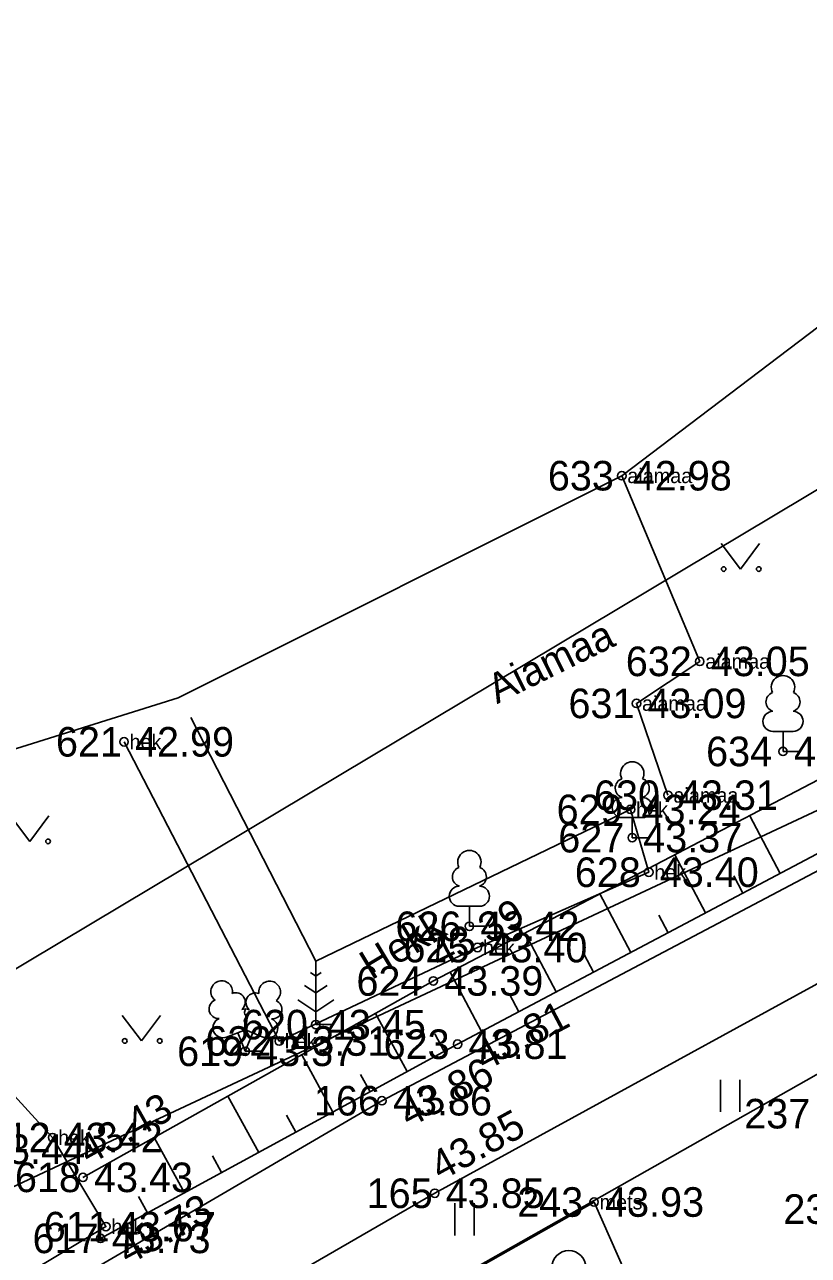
# Model space of a CAD drawing. Extents: x 505800 to 507326, y 6540058 to 6542128.
# Drawn here: x 506386.44 to 506404.99, y 6540355.67 to 6540384.81 of the extents above; entities that cross this region are included whole.
import ezdxf

# ---------------------------------------------------------------- set-up
doc = ezdxf.new("R2010")
doc.units = 0
for name, color, linetype in [('HALJASTUS', 7, 'Continuous'), ('KORGUS-EH2000', 7, 'Continuous'), ('MAAMUDEL', 7, 'Continuous'), ('MOOTKORG-EH2000', 7, 'Continuous'), ('MOOTMPUNKT', 7, 'Continuous'), ('MOOTNR', 7, 'Continuous'), ('MOOTPIIR', 7, 'Continuous'), ('MPOHULIIN', 7, 'Continuous'), ('PIIR', 7, 'Continuous'), ('PUU', 7, 'Continuous'), ('RELJEEF', 7, 'Continuous'), ('TEE', 7, 'Continuous')]:
    doc.layers.add(name, color=color, linetype=linetype)

msp = doc.modelspace()

# ---------------------------------------------------------------- linework, layer by layer
at = {"layer": 'HALJASTUS'}
for p, q in [((506402.92, 6540372.527), (506403.383, 6540371.92)), ((506403.383, 6540371.92), (506403.829, 6540372.527)), ((506386.104, 6540366.077), (506386.568, 6540365.471)), ((506386.568, 6540365.471), (506387.013, 6540366.077)), ((506388.747, 6540361.35), (506389.21, 6540360.744)), ((506389.21, 6540360.744), (506389.656, 6540361.35)), ((506402.906, 6540359.823), (506402.906, 6540359.062)), ((506403.361, 6540359.823), (506403.361, 6540359.062)), ((506396.621, 6540356.899), (506396.621, 6540356.137)), ((506397.076, 6540356.899), (506397.076, 6540356.137))]:
    msp.add_line(p, q, dxfattribs=at)
for points in [[(506400.572, 6540374.13), (506402.416, 6540369.732), (506400.919, 6540368.738), (506401.664, 6540366.563)], [(506390.376, 6540368.401), (506393.333, 6540362.631), (506400.779, 6540366.227), (506401.21, 6540364.74), (506397.155, 6540362.956), (506392.467, 6540360.742), (506388.793, 6540367.828)], [(506383.074, 6540362.871), (506387.104, 6540358.456), (506388.363, 6540356.347), (506379.473, 6540351.019), (506371.247, 6540346.037), (506370.193, 6540346.236), (506368.863, 6540348.749), (506383.542, 6540357.221), (506381.795, 6540361.969), (506383.074, 6540362.871)], [(506391.999, 6540341.498), (506392.008, 6540346.055), (506393.81, 6540353.469), (506399.916, 6540356.93), (506402.307, 6540351.523), (506409.831, 6540355.263), (506411.426, 6540354.112)]]:
    msp.add_lwpolyline(points, dxfattribs=at)
for centre, radius in [((506402.982, 6540371.92), 0.055), ((506403.811, 6540371.92), 0.055), ((506386.995, 6540365.471), 0.055), ((506388.809, 6540360.744), 0.055), ((506389.638, 6540360.744), 0.055), ((506399.317, 6540355.381), 0.4)]:
    msp.add_circle(centre, radius, dxfattribs=at)
at = {"layer": 'KORGUS-EH2000'}
for centre in [(506400.572, 6540374.13), (506402.416, 6540369.732), (506400.919, 6540368.738), (506388.793, 6540367.828), (506404.386, 6540367.6), (506401.664, 6540366.563), (506400.779, 6540366.227), (506400.819, 6540365.558), (506401.21, 6540364.74), (506396.965, 6540363.459), (506397.155, 6540362.956), (506396.112, 6540362.165), (506393.333, 6540361.131), (506392.467, 6540360.742), (506396.686, 6540360.667), (506391.66, 6540360.499), (506394.897, 6540359.329), (506387.104, 6540358.456), (506387.822, 6540357.514), (506396.144, 6540357.137), (506399.916, 6540356.93), (506388.363, 6540356.347), (506388.239, 6540356.069)]:
    msp.add_circle(centre, 0.1, dxfattribs=at)
at = {"layer": 'MOOTMPUNKT'}
for centre in [(506400.572, 6540374.13), (506402.416, 6540369.732), (506400.919, 6540368.738), (506388.793, 6540367.828), (506404.386, 6540367.6), (506401.664, 6540366.563), (506400.779, 6540366.227), (506400.819, 6540365.558), (506401.21, 6540364.74), (506396.965, 6540363.459), (506397.155, 6540362.956), (506396.112, 6540362.165), (506393.333, 6540361.131), (506392.467, 6540360.742), (506396.686, 6540360.667), (506391.66, 6540360.499), (506394.897, 6540359.329), (506387.104, 6540358.456), (506387.822, 6540357.514), (506396.144, 6540357.137), (506399.916, 6540356.93), (506388.363, 6540356.347), (506388.239, 6540356.069)]:
    msp.add_circle(centre, 0.1, dxfattribs=at)
at = {"layer": 'MOOTPIIR'}
msp.add_lwpolyline([(506240.253, 6540270.959), (506245.955, 6540263.864), (506266.133, 6540270.794), (506275.983, 6540276.683), (506285.511, 6540285.657), (506298.843, 6540299.878), (506301.086, 6540304.525), (506297.722, 6540312.738), (506305.023, 6540318.445), (506309.38, 6540311.746), (506312.325, 6540315.185), (506338.029, 6540330.648), (506336.908, 6540340.183), (506347.357, 6540347.554), (506370.89, 6540361.705), (506382.389, 6540366.462), (506390.076, 6540368.866), (506400.572, 6540374.13), (506410.565, 6540381.71), (506441.143, 6540393.151), (506453.59, 6540403.335), (506461.402, 6540393.473), (506495.448, 6540402.285)], dxfattribs=at)
at = {"layer": 'MPOHULIIN'}
msp.add_line((506372.493, 6540354.233), (506416.453, 6540380.536), dxfattribs=at)
at = {"layer": 'PIIR'}
msp.add_lwpolyline([(506326.14, 6540370.11), (506324.04, 6540375.18), (506354.05, 6540393.57), (506395.54, 6540418.74), (506427.6, 6540438.79), (506429.21, 6540436.36), (506458.7, 6540391.28), (506340.34, 6540335.82)], close=True, dxfattribs=at)
for points in [[(506215.95, 6540254.34), (506268.55, 6540273.9), (506274.54, 6540277.85), (506304.35, 6540308.95), (506340.34, 6540335.82), (506458.7, 6540391.28), (506563.96, 6540420.02)], [(506497.85, 6540391.32), (506462.8, 6540384.69), (506453.27, 6540382.76), (506413.82, 6540364.84), (506374.55, 6540342.6), (506353.59, 6540332.53), (506318.07, 6540309.28), (506308, 6540301.95), (506281.65, 6540275.05), (506272.39, 6540267.75), (506224.13, 6540249.92)], [(506224.13, 6540249.92), (506272.39, 6540267.75), (506281.65, 6540275.05), (506308, 6540301.95), (506318.07, 6540309.28), (506353.59, 6540332.53), (506374.55, 6540342.6), (506413.82, 6540364.84), (506453.27, 6540382.76), (506462.8, 6540384.69), (506495.14, 6540337.45), (506342.85, 6540237.27), (506260.72, 6540195.9), (506215.68, 6540179.69)]]:
    msp.add_lwpolyline(points, dxfattribs=at)
at = {"layer": 'PUU'}
for p, q in [((506404.626, 6540368.075), (506404.146, 6540368.075)), ((506404.386, 6540367.6), (506404.386, 6540368.075)), ((506404.766, 6540367.6), (506404.386, 6540367.6)), ((506401.059, 6540366.033), (506400.579, 6540366.033)), ((506400.819, 6540365.558), (506400.819, 6540366.033)), ((506401.199, 6540365.558), (506400.819, 6540365.558)), ((506397.205, 6540363.934), (506396.725, 6540363.934)), ((506396.965, 6540363.459), (506396.965, 6540363.934)), ((506397.345, 6540363.459), (506396.965, 6540363.459)), ((506393.333, 6540362.281), (506393.208, 6540362.364)), ((506393.333, 6540362.631), (506393.333, 6540361.131)), ((506393.457, 6540362.364), (506393.333, 6540362.281)), ((506393.333, 6540361.881), (506393.066, 6540362.059)), ((506393.599, 6540362.059), (506393.333, 6540361.881)), ((506392.909, 6540361.72), (506393.333, 6540361.437)), ((506393.333, 6540361.437), (506393.757, 6540361.72)), ((506391.22, 6540360.834), (506391.665, 6540361.009)), ((506391.66, 6540360.499), (506391.485, 6540360.939)), ((506391.66, 6540360.499), (506391.84, 6540360.939)), ((506391.665, 6540361.009), (506392.105, 6540360.829)), ((506393.693, 6540361.131), (506393.333, 6540361.131)), ((506392.04, 6540360.499), (506391.66, 6540360.499))]:
    msp.add_line(p, q, dxfattribs=at)
msp.add_lwpolyline([(506391.665, 6540361.504), (506391.645, 6540361.429), (506391.645, 6540361.409), (506391.655, 6540361.379), (506391.675, 6540361.344), (506391.68, 6540361.324), (506391.665, 6540361.289), (506391.64, 6540361.239), (506391.635, 6540361.214), (506391.64, 6540361.199), (506391.65, 6540361.169), (506391.685, 6540361.109), (506391.69, 6540361.089), (506391.685, 6540361.069), (506391.67, 6540361.034), (506391.665, 6540361.009)], dxfattribs=at)
for centre, radius, start, end in [((506404.386, 6540369.12), 0.277, 332.5799, 207.4201), ((506404.216, 6540368.773), 0.233, 109.0217, 253.1415), ((506404.556, 6540368.773), 0.233, 286.8508, 70.9859), ((506404.148, 6540368.312), 0.238, 90.0016, 269.3953), ((506404.623, 6540368.312), 0.238, 270.6047, 89.9984), ((506400.819, 6540367.078), 0.277, 332.5799, 207.4201), ((506400.649, 6540366.731), 0.233, 109.0217, 253.1415), ((506400.989, 6540366.731), 0.233, 286.8508, 70.9859), ((506400.582, 6540366.271), 0.238, 90.0016, 269.3953), ((506401.057, 6540366.271), 0.238, 270.6047, 89.9984), ((506396.965, 6540364.979), 0.277, 332.5799, 207.4201), ((506396.795, 6540364.631), 0.233, 109.0217, 253.1415), ((506397.135, 6540364.631), 0.233, 286.8508, 70.9859), ((506396.727, 6540364.171), 0.238, 90.0016, 269.3953), ((506397.202, 6540364.171), 0.238, 270.6047, 89.9984), ((506391.103, 6540361.913), 0.256, 111.5027, 232.5173), ((506391.103, 6540361.913), 0.256, 350.4856, 111.5002), ((506392.239, 6540361.904), 0.256, 67.6168, 188.6314), ((506392.239, 6540361.904), 0.256, 306.5997, 67.6143), ((506391.438, 6540361.662), 0.224, 308.5041, 111.5725), ((506391.901, 6540361.658), 0.225, 67.7016, 230.5126), ((506391.029, 6540361.501), 0.224, 111.4304, 274.4987), ((506391.664, 6540361.266), 0.237, 66.7655, 111.5015), ((506392.306, 6540361.492), 0.224, 264.6183, 67.6866), ((506391.134, 6540361.057), 0.237, 111.5014, 291.5004), ((506392.195, 6540361.049), 0.237, 247.6166, 67.6155)]:
    msp.add_arc(centre, radius, start, end, dxfattribs=at)
at = {"layer": 'RELJEEF'}
for p, q in [((506404.322, 6540364.713), (506403.598, 6540366.079)), ((506402.554, 6540363.777), (506401.826, 6540365.152)), ((506403.438, 6540364.245), (506403.22, 6540364.656)), ((506400.787, 6540362.84), (506400.053, 6540364.225)), ((506401.671, 6540363.308), (506401.451, 6540363.722)), ((506399.02, 6540361.904), (506398.281, 6540363.298)), ((506399.904, 6540362.372), (506399.683, 6540362.789)), ((506397.253, 6540360.967), (506396.508, 6540362.372)), ((506398.136, 6540361.435), (506397.914, 6540361.855)), ((506395.493, 6540360.017), (506394.742, 6540361.396)), ((506396.371, 6540360.495), (506396.144, 6540360.912)), ((506393.736, 6540359.061), (506392.998, 6540360.418)), ((506394.615, 6540359.539), (506394.391, 6540359.949)), ((506391.98, 6540358.105), (506391.253, 6540359.439)), ((506392.858, 6540358.583), (506392.638, 6540358.987)), ((506390.223, 6540357.149), (506389.509, 6540358.46)), ((506391.101, 6540357.627), (506390.885, 6540358.024)), ((506389.345, 6540356.671), (506389.132, 6540357.061))]:
    msp.add_line(p, q, dxfattribs=at)
for points in [[(506556.207, 6540417.529), (506548.446, 6540415.756), (506537.177, 6540411.287), (506507.092, 6540401.356), (506493.818, 6540397.458), (506479.74, 6540393.488), (506463.711, 6540390.977), (506454.162, 6540389.588), (506445.961, 6540387.82), (506436.644, 6540384.929), (506428.217, 6540381.232), (506425.206, 6540377.812), (506418.006, 6540373.612), (506396.112, 6540362.165), (506387.822, 6540357.514)], [(506556.207, 6540417.529), (506549.32, 6540414.59), (506538.05, 6540410.165), (506520.494, 6540403.746), (506508.114, 6540399.97), (506494.198, 6540395.848), (506479.734, 6540392.802), (506464.199, 6540389.877), (506454.62, 6540387.729), (506446.277, 6540385.845), (506437.645, 6540382.533), (506432.878, 6540380.89), (506430.375, 6540378.218), (506418.514, 6540372.235), (506396.686, 6540360.667), (506388.239, 6540356.069)]]:
    msp.add_lwpolyline(points, dxfattribs=at)
at = {"layer": 'TEE'}
for points in [[(506478.706, 6540392.058), (506464.091, 6540389.4), (506454.678, 6540387.173), (506446.264, 6540384.451), (506435.18, 6540379.372), (506420.092, 6540372.182), (506407.957, 6540366.228), (506394.897, 6540359.329), (506383.759, 6540352.819), (506372.647, 6540346.37), (506363.224, 6540341.99), (506352.182, 6540336.393), (506347.174, 6540333.201), (506340.898, 6540329.111), (506329.323, 6540321.237)], [(506479.167, 6540389.797), (506464.651, 6540387.028), (506455.166, 6540384.708), (506447.071, 6540382.035), (506436.402, 6540377.232), (506421.232, 6540370.083), (506409.03, 6540364.194), (506396.144, 6540357.137), (506385.127, 6540350.766), (506373.749, 6540344.271), (506364.374, 6540339.718), (506353.506, 6540334.212), (506348.479, 6540331.101), (506342.338, 6540327.065), (506330.786, 6540319.25)]]:
    msp.add_lwpolyline(points, dxfattribs=at)

# ---------------------------------------------------------------- texts
at = {"layer": 'HALJASTUS'}
for s, rotation, p in [('Aiamaa', 26.2166, (506397.617, 6540368.717)), ('Hekk', 30.9694, (506394.648, 6540362.175))]:
    msp.add_text(s, height=0.7, rotation=rotation, dxfattribs=at).set_placement(p)
at = {"layer": 'KORGUS-EH2000'}
for s, p in [(' 42.98', (506400.572, 6540373.78)), (' 43.09', (506400.919, 6540368.388)), (' 42.99', (506388.793, 6540367.478)), (' 43.93', (506399.916, 6540356.58)), (' 43.67', (506388.363, 6540355.997))]:
    msp.add_text(s, height=0.7, dxfattribs=at).set_placement(p)
for s, rotation, p in [(' 43.39', 27.6032, (506396.031, 6540362.32)), (' 43.81', 27.922, (506397.096, 6540359.893)), (' 43.86', 27.8447, (506395.305, 6540358.555)), (' 43.43', 29.2905, (506387.736, 6540357.667)), (' 43.85', 28.7058, (506396.06, 6540357.291)), (' 43.73', 28.559, (506388.658, 6540355.301))]:
    msp.add_text(s, height=0.7, rotation=rotation, dxfattribs=at).set_placement(p)
at = {"layer": 'MAAMUDEL'}
for s, p in [(' aiamaa', (506400.572, 6540373.955)), (' aiamaa', (506402.416, 6540369.558)), (' aiamaa', (506400.919, 6540368.563)), (' hek', (506388.793, 6540367.653)), (' aiamaa', (506401.664, 6540366.388)), (' hek', (506400.779, 6540366.052)), (' hek', (506401.21, 6540364.565)), (' hek', (506397.155, 6540362.781)), (' hek', (506392.467, 6540360.567)), (' hek', (506387.104, 6540358.281)), (' mets', (506399.916, 6540356.755)), (' hek', (506388.363, 6540356.172))]:
    msp.add_text(s, height=0.35, dxfattribs=at).set_placement(p)
at = {"layer": 'MOOTKORG-EH2000'}
for s, p in [(' 42.98', (506400.572, 6540373.78)), (' 43.05', (506402.416, 6540369.383)), (' 43.09', (506400.919, 6540368.388)), (' 42.99', (506388.793, 6540367.478)), (' 43.44', (506404.386, 6540367.25)), (' 43.31', (506401.664, 6540366.213)), (' 43.24', (506400.779, 6540365.877)), (' 43.37', (506400.819, 6540365.208)), (' 43.40', (506401.21, 6540364.39)), (' 43.42', (506396.965, 6540363.109)), (' 43.40', (506397.155, 6540362.606)), (' 43.39', (506396.112, 6540361.815)), (' 43.45', (506393.333, 6540360.781)), (' 43.31', (506392.467, 6540360.393)), (' 43.81', (506396.686, 6540360.317)), (' 43.37', (506391.66, 6540360.149)), (' 43.86', (506394.897, 6540358.979)), (' 43.42', (506387.104, 6540358.106)), (' 43.44', (506385.267, 6540357.831)), (' 43.43', (506387.822, 6540357.164)), (' 43.85', (506396.144, 6540356.787)), (' 43.93', (506399.916, 6540356.58)), (' 43.67', (506388.363, 6540355.997)), (' 43.73', (506388.239, 6540355.719))]:
    msp.add_text(s, height=0.7, dxfattribs=at).set_placement(p)
at = {"layer": 'MOOTNR'}
for s, p in [('633 ', (506398.822, 6540373.78)), ('632 ', (506400.666, 6540369.383)), ('631 ', (506399.309, 6540368.388)), ('621 ', (506387.183, 6540367.478)), ('634 ', (506402.566, 6540367.25)), ('630 ', (506399.914, 6540366.213)), ('629 ', (506399.029, 6540365.877)), ('627 ', (506399.069, 6540365.208)), ('628 ', (506399.46, 6540364.39)), ('626 ', (506395.215, 6540363.109)), ('625 ', (506395.405, 6540362.606)), ('624 ', (506394.292, 6540361.815)), ('620 ', (506391.583, 6540360.781)), ('622 ', (506390.717, 6540360.393)), ('623 ', (506394.936, 6540360.317)), ('619 ', (506390.05, 6540360.149)), ('166 ', (506393.287, 6540358.979)), ('237 ', (506403.468, 6540358.672)), ('612 ', (506385.494, 6540358.106)), ('618 ', (506386.212, 6540357.164)), ('165 ', (506394.534, 6540356.787)), ('243 ', (506398.097, 6540356.58)), ('238 ', (506404.394, 6540356.413)), ('611 ', (506386.893, 6540355.997)), ('617 ', (506386.629, 6540355.719))]:
    msp.add_text(s, height=0.7, dxfattribs=at).set_placement(p)

doc.saveas('drawing.dxf')
